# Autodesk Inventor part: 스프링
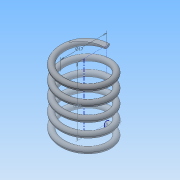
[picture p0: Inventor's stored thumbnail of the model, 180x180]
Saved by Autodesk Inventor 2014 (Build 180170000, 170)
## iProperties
Created: 2016-03
Part Number: 스프링
Material: 일반
Document SubType Name: Modeling
Designer: net
Density: 1 g/cm^3
Appearance: 기본값
Author: net
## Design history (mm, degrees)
sketch "스케치1"
  geometry: L1 (0, 0)-(8.5, 0); L2 (8.5, 0)-(8.5, 25); L3 (8.5, 25)-(0, 25); L4 (0, 25)-(0, 0); C1 r 1 at (8.5, 0)
  constraints: 8 end point, 2 parallel, 1 centre point, 1 coincident, 1 horizontal, 1 perpendicular
  dimensions: "d0" = 2 diameter of C1; "d1" = 25 distance of L3.end L1.start (derived); "d2" = 17 diameter of L2 L4
feature "코일1" sketch "스케치1" pitch "d3" = 10; turns "d5" = 5; dims "d4" = 25 (= d1), "d6" = 0, angle "d7" = 90 deg, angle "d8" = 90 deg, "d9" = 0, "d10" = 0
sketch "스케치2"
  geometry: L1 (0, 7.5)-(0, 9.5) reference; 1 further point
  constraints: 1 vertical alignment
extrude "돌출1" cut sketch "스케치2" stored distance "d11" = 10; taper "d12" = 0 deg
node "작업 평면1"
sketch "스케치3"
  geometry: L1 (0, -2)-(0, 0) reference; 1 further point
  constraints: 1 vertical alignment
extrude "돌출2" cut sketch "스케치3" stored distance "d13" = 10; taper "d14" = 0 deg
node "솔리드1"
node "절단 모서리 투영1"
node "절단 모서리 투영2"
